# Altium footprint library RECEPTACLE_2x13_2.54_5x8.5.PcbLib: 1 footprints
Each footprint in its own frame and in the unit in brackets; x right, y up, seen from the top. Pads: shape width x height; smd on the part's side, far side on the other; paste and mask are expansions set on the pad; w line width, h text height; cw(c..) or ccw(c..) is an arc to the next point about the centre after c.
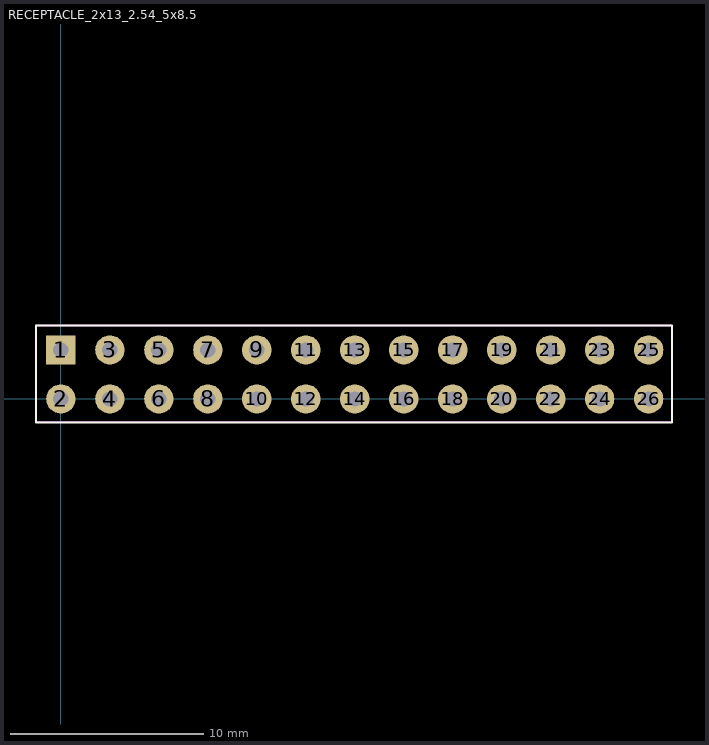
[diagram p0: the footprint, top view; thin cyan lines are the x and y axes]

## RECEPTACLE_2x13_2.54_5x8.5 [mil]
pads (26):
  rect 60x60 hole 31.5: 1(0,100)
  round 60 hole 31.5: 2(0,0) 3(100,100) 4(100,0) 5(200,100) 6(200,0) 7(300,100) 8(300,0) 9(400,100) 10(400,0) 11(500,100) 12(500,0) 13(600,100) 14(600,0) 15(700,100) 16(700,0) 17(800,100) 18(800,0) 19(900,100) 20(900,0) 21(1000,100) 22(1000,0) 23(1100,100) 24(1100,0) 25(1200,100) 26(1200,0)
Top Overlay:
  lines w3.94: -51.18,-47.64 -51.18,149.61 1248.03,149.61 1248.03,-47.64 -51.18,-47.64
Top Assembly:
  lines w3.94: -51.18,-47.24 1248.03,-47.24 1248.03,149.61 -51.18,149.61 -51.18,-47.24
  text ".Designator" at 413.39,39.37 h35.43
  text "1" at -11.81,78.74 h39.37
  text "2" at -19.68,-23.62 h39.37
  text "3" at 80.71,76.77 h39.37
  text "4" at 78.74,-23.62 h39.37
3D body "2x13_2.54mm_5x8.5.step": height 330.71, standoff -106.3, extent -51.18,-48.82 1248.82,151.18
